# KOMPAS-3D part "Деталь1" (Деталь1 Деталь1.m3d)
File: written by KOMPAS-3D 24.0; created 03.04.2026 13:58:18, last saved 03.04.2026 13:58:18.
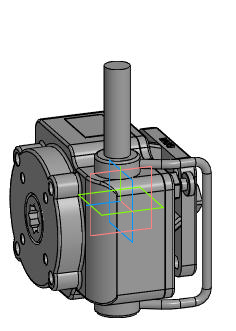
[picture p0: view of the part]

Document properties: Автор: R2D2; Полное имя файла: E:\Работа\Зайцев\Аксессуары для пневмоприводов\Ручной дублер DN.ru\MON2-450-T28-ISO Ручной дублер DN.ru\исходные материалы\Деталь1 Деталь1.m3d

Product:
- Part/product: Деталь1
    Масса: 10.922817
    additional columns: Типовые

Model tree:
1. Операция без истории:1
